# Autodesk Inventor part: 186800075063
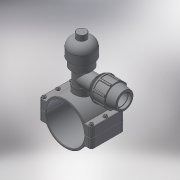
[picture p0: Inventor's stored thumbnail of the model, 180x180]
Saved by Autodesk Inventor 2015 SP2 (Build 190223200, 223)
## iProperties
Created: 2017-05
Part Number: 186800075063
Material: Generic
Description: PLASSON MECHANICAL TAPPING VALVE 75-63
Document SubType Name: Modeling
Designer: KIM
Density: 1 g/cm^3
Appearance: Default
Author: KIM
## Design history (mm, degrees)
derived "18680.ipt"
feature "Solid1::18680.ipt"
feature "Solid2::18680.ipt"
tag "TaggingFeature1"
body "Solid1"
other parameters: "d0" = 93.75, "d1" = 122, "d2" = 37.5, "d3" = 75, "d4" = 98, "d5" = 0, "d6" = 6.1, "d7" = 122, "d8" = 0.1, "d10" = 0, "d11" = 0.75, "d14" = 58.2985, "d20" = 0.75, "d23" = 0.75, "d37" = 8, "d38" = 45.5, "d39" = 0, "d40" = 3, "d41" = 5, "d42" = 0, "d43" = 6, "d44" = 3, "d45" = 0, "d46" = 0.75, "d51" = 67, "d52" = 44.845, "d53" = 21, "d54" = 0, "d57" = 0, "d58" = 81, "d60" = 0, "d63" = 8, "d66" = 82, "d67" = 63, "d68" = 16.66667, "d70" = 113, "d71" = 84.75, "d72" = 2.85714, "d73" = 90.4, "d74" = 120 deg, "d75" = 81.9, "d76" = 10 deg, "d77" = 101.7, "d80" = 40.95, "d82" = 11, "d87" = 28.57143, "d90" = 105.09, "d91" = 35 deg, "d92" = 17.5 deg, "d94" = 0, "d96" = 360 deg, "d98" = 1.26, "d99" = 121, "d100" = 50.85, "d101" = 135 deg, "d102" = 2.26, "d105" = 5.65, "d106" = 0, "d107" = 0.1, "d109" = 58.2985, "d112" = 34.85714, "d113" = 6.66667, "d116" = 0, "d121" = 53.814, "d122" = 89.69, "d123" = 76.2365, "d124" = 45 deg, "d125" = 219.6, "d126" = 244, "d127" = 146.4, "d128" = 1, "d129" = 65, "d_" = 75, "G_" = 44.845, "A_" = 67, "L_" = 122, "L_1" = 98, "l_2" = 21, "d_1" = 63, "E_" = 113, "H_1" = 65, "H_2" = 244
